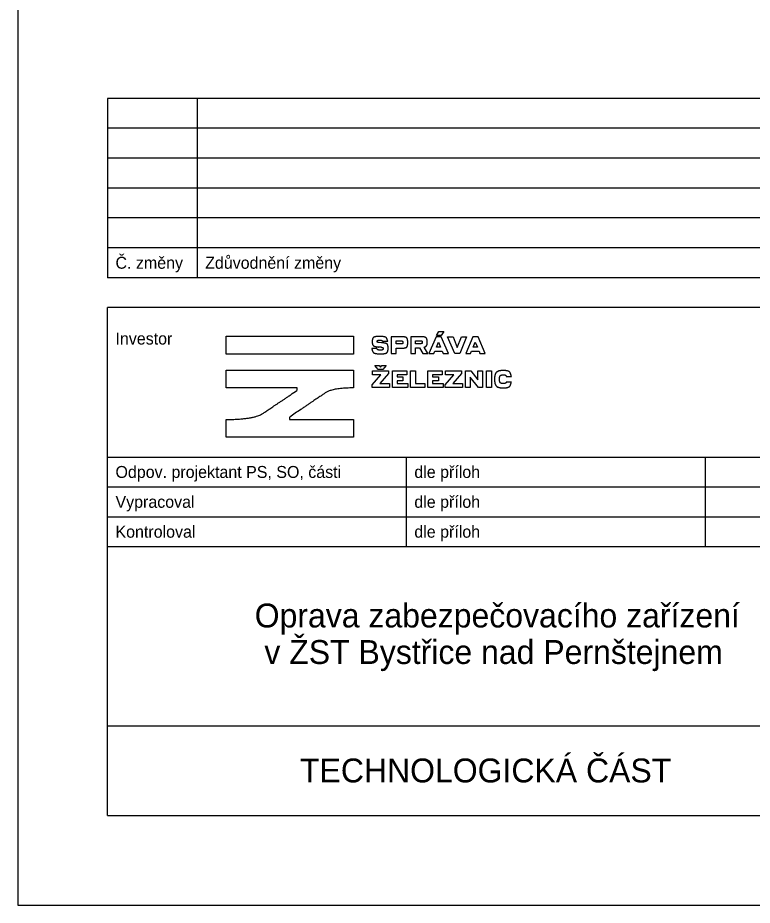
# Model space of a CAD drawing. Extents: x -790471 to -790261, y -986448 to -986151.
# Drawn here: x -790470.6 to -790347.7, y -986447.6 to -986299.1 of the extents above; entities that cross this region are included whole.
import ezdxf

# ---------------------------------------------------------------- set-up
doc = ezdxf.new("R2010")
doc.units = 0
for name, color, linetype in [('logo_sprava_zeleznic', 7, 'Continuous'), ('Ramečky', 7, 'Continuous'), ('Rámečky-tisk', 7, 'Continuous'), ('Text', 7, 'Continuous'), ('Text barevný', 7, 'Continuous')]:
    doc.layers.add(name, color=color, linetype=linetype)

msp = doc.modelspace()

# ---------------------------------------------------------------- linework, layer by layer
at = {"layer": 'logo_sprava_zeleznic'}
for p, q in [((-790400.56, -986352.26), (-790400.12, -986351.6)), ((-790400.12, -986351.6), (-790399.3, -986351.6)), ((-790399.3, -986351.6), (-790399.78, -986352.26)), ((-790409.51, -986353.23), (-790408.69, -986353.23)), ((-790399.78, -986352.26), (-790400.56, -986352.26)), ((-790398.7, -986352.48), (-790397.76, -986352.48)), ((-790397.49, -986355.29), (-790398.7, -986352.48)), ((-790397.76, -986352.48), (-790397.05, -986354.28)), ((-790397.05, -986354.28), (-790396.34, -986352.48)), ((-790395.49, -986352.48), (-790396.64, -986355.29)), ((-790396.34, -986352.48), (-790395.49, -986352.48)), ((-790410.51, -986354.45), (-790411.36, -986354.45)), ((-790409.76, -986353.48), (-790410.15, -986353.45)), ((-790396.64, -986355.29), (-790397.49, -986355.29)), ((-790410.29, -986357.96), (-790410.83, -986357.28)), ((-790410.83, -986357.28), (-790410.14, -986357.28)), ((-790410.14, -986357.28), (-790409.91, -986357.56)), ((-790409.91, -986357.56), (-790409.68, -986357.28)), ((-790409.68, -986357.28), (-790408.97, -986357.28)), ((-790408.97, -986357.28), (-790409.53, -986357.96)), ((-790411.3, -986360.53), (-790409.84, -986358.86)), ((-790411.26, -986358.17), (-790408.55, -986358.17)), ((-790411.26, -986358.86), (-790411.26, -986358.17)), ((-790409.84, -986358.86), (-790411.26, -986358.86)), ((-790409.53, -986357.96), (-790410.29, -986357.96)), ((-790408.55, -986358.63), (-790410.02, -986360.29)), ((-790408.55, -986358.17), (-790408.55, -986358.63)), ((-790407.92, -986358.17), (-790405.49, -986358.17)), ((-790407.92, -986360.99), (-790407.92, -986358.17)), ((-790405.49, -986358.83), (-790407.1, -986358.83)), ((-790407.1, -986358.83), (-790407.1, -986359.2)), ((-790407.1, -986359.2), (-790406.14, -986359.2)), ((-790406.14, -986359.2), (-790406.14, -986359.87)), ((-790405.49, -986358.17), (-790405.49, -986358.83)), ((-790404.86, -986358.17), (-790404.05, -986358.17)), ((-790404.86, -986360.99), (-790404.86, -986358.17)), ((-790404.05, -986358.17), (-790404.05, -986360.28)), ((-790401.99, -986358.17), (-790399.57, -986358.17)), ((-790401.99, -986360.99), (-790401.99, -986358.17)), ((-790399.57, -986358.83), (-790401.18, -986358.83)), ((-790401.18, -986358.83), (-790401.18, -986359.2)), ((-790401.18, -986359.2), (-790400.22, -986359.2)), ((-790400.22, -986359.2), (-790400.22, -986359.87)), ((-790399.57, -986358.17), (-790399.57, -986358.83)), ((-790399.07, -986360.53), (-790397.61, -986358.86)), ((-790399.03, -986358.17), (-790396.33, -986358.17)), ((-790399.03, -986358.86), (-790399.03, -986358.17)), ((-790397.61, -986358.86), (-790399.03, -986358.86)), ((-790396.33, -986358.63), (-790397.8, -986360.29)), ((-790396.33, -986358.17), (-790396.33, -986358.63)), ((-790395.69, -986358.17), (-790394.78, -986358.17)), ((-790395.69, -986360.99), (-790395.69, -986358.17)), ((-790393.53, -986360.99), (-790394.89, -986359.26)), ((-790394.89, -986359.26), (-790394.89, -986360.99)), ((-790394.78, -986358.17), (-790393.63, -986359.68)), ((-790393.63, -986359.68), (-790393.63, -986358.17)), ((-790393.63, -986358.17), (-790392.85, -986358.17)), ((-790392.85, -986358.17), (-790392.85, -986360.99)), ((-790388.84, -986359.12), (-790388.01, -986359.12)), ((-790411.3, -986360.99), (-790411.3, -986360.53)), ((-790410.02, -986360.29), (-790408.39, -986360.29)), ((-790408.39, -986360.29), (-790408.39, -986360.99)), ((-790406.14, -986359.87), (-790407.1, -986359.87)), ((-790407.1, -986359.87), (-790407.1, -986360.3)), ((-790407.1, -986360.3), (-790405.34, -986360.3)), ((-790405.34, -986360.3), (-790405.34, -986360.99)), ((-790404.05, -986360.28), (-790402.47, -986360.28)), ((-790402.47, -986360.28), (-790402.47, -986360.99)), ((-790400.22, -986359.87), (-790401.18, -986359.87)), ((-790401.18, -986359.87), (-790401.18, -986360.3)), ((-790401.18, -986360.3), (-790399.41, -986360.3)), ((-790399.41, -986360.3), (-790399.41, -986360.99)), ((-790399.07, -986360.99), (-790399.07, -986360.53)), ((-790397.8, -986360.29), (-790396.16, -986360.29)), ((-790396.16, -986360.29), (-790396.16, -986360.99)), ((-790388.01, -986360.05), (-790388.83, -986360.05)), ((-790408.39, -986360.99), (-790411.3, -986360.99)), ((-790405.34, -986360.99), (-790407.92, -986360.99)), ((-790402.47, -986360.99), (-790404.86, -986360.99)), ((-790399.41, -986360.99), (-790401.99, -986360.99)), ((-790396.16, -986360.99), (-790399.07, -986360.99)), ((-790394.89, -986360.99), (-790395.69, -986360.99)), ((-790392.85, -986360.99), (-790393.53, -986360.99))]:
    msp.add_line(p, q, dxfattribs=at)
for points in [[(-790435.73, -986352.4), (-790414.41, -986352.4), (-790414.41, -986355.38), (-790435.73, -986355.38)], [(-790401.8, -986355.29), (-790400.98, -986355.29), (-790400.82, -986354.89), (-790399.57, -986354.89), (-790399.41, -986355.29), (-790398.53, -986355.29), (-790399.73, -986352.48), (-790400.6, -986352.48)], [(-790395.65, -986355.29), (-790394.83, -986355.29), (-790394.66, -986354.89), (-790393.42, -986354.89), (-790393.26, -986355.29), (-790392.38, -986355.29), (-790393.57, -986352.48), (-790394.45, -986352.48)], [(-790400.19, -986353.39), (-790399.85, -986354.23), (-790400.54, -986354.23)], [(-790394.04, -986353.39), (-790393.7, -986354.23), (-790394.39, -986354.23)], [(-790392.16, -986358.17), (-790391.35, -986358.17), (-790391.35, -986360.99), (-790392.16, -986360.99)]]:
    msp.add_lwpolyline(points, close=True, dxfattribs=at)
for points in [[(-790406.38, -986352.48), (-790408.11, -986352.48), (-790408.11, -986355.29), (-790407.3, -986355.29), (-790407.3, -986354.39), (-790406.38, -986354.39)], [(-790406.48, -986353.69), (-790407.3, -986353.69), (-790407.3, -986353.17), (-790406.48, -986353.17)], [(-790403.12, -986352.48), (-790404.84, -986352.48), (-790404.84, -986355.29), (-790404.03, -986355.29), (-790404.03, -986354.31), (-790403.39, -986354.31), (-790402.84, -986355.29), (-790401.98, -986355.29), (-790402.59, -986354.22)], [(-790403.22, -986353.64), (-790404.03, -986353.64), (-790404.03, -986353.16), (-790403.22, -986353.16)], [(-790423.87, -986361.46), (-790423.87, -986361.04), (-790435.73, -986361.04), (-790435.73, -986358.07), (-790414.41, -986358.07), (-790414.41, -986361.04)], [(-790425.1, -986365.91), (-790425.1, -986366.32), (-790414.41, -986366.32), (-790414.41, -986369.3), (-790435.73, -986369.3), (-790435.73, -986366.32), (-790435.71, -986366.32)]]:
    msp.add_lwpolyline(points, dxfattribs=at)
for centre, radius, start, end in [((-790411.9, -986375.14), 21.01, 84.2634, 85.3384), ((-790461.18, -986308.6), 64.69, 304.0901, 305.2133), ((-790124.63, -986802.54), 530.02, 124.292, 124.5333)]:
    msp.add_arc(centre, radius, start, end, dxfattribs=at)
for points in [[(-790410.05, -986352.42), (-790410.77, -986352.42), (-790411.29, -986352.71), (-790411.29, -986353.28)], [(-790411.29, -986353.28), (-790411.29, -986353.83), (-790410.87, -986354.14), (-790410.19, -986354.2)], [(-790410.46, -986353.24), (-790410.46, -986353.12), (-790410.3, -986353.06), (-790410.05, -986353.06)], [(-790410.15, -986353.45), (-790410.35, -986353.43), (-790410.46, -986353.36), (-790410.46, -986353.24)], [(-790408.69, -986353.23), (-790408.77, -986352.87), (-790409.09, -986352.42), (-790410.05, -986352.42)], [(-790410.05, -986353.06), (-790409.73, -986353.06), (-790409.55, -986353.17), (-790409.51, -986353.23)], [(-790406.48, -986353.17), (-790406.27, -986353.17), (-790406.17, -986353.26), (-790406.17, -986353.43)], [(-790405.34, -986353.43), (-790405.34, -986352.8), (-790405.73, -986352.48), (-790406.38, -986352.48)], [(-790403.22, -986353.16), (-790403.02, -986353.16), (-790402.91, -986353.23), (-790402.91, -986353.4)], [(-790402.08, -986353.4), (-790402.08, -986352.79), (-790402.49, -986352.48), (-790403.12, -986352.48)], [(-790411.36, -986354.45), (-790411.29, -986354.84), (-790410.93, -986355.34), (-790409.92, -986355.34)], [(-790409.92, -986354.71), (-790410.28, -986354.71), (-790410.46, -986354.57), (-790410.51, -986354.45)], [(-790409.92, -986355.34), (-790409.08, -986355.34), (-790408.63, -986355), (-790408.63, -986354.4)], [(-790409.47, -986354.46), (-790409.47, -986354.61), (-790409.6, -986354.71), (-790409.92, -986354.71)], [(-790409.8, -986354.23), (-790409.6, -986354.26), (-790409.47, -986354.31), (-790409.47, -986354.46)], [(-790408.63, -986354.4), (-790408.63, -986353.79), (-790409.03, -986353.53), (-790409.76, -986353.48)], [(-790406.17, -986353.43), (-790406.17, -986353.59), (-790406.27, -986353.69), (-790406.48, -986353.69)], [(-790406.38, -986354.39), (-790405.73, -986354.39), (-790405.34, -986354.06), (-790405.34, -986353.43)], [(-790402.91, -986353.4), (-790402.91, -986353.55), (-790403.02, -986353.64), (-790403.22, -986353.64)], [(-790402.59, -986354.22), (-790402.27, -986354.08), (-790402.08, -986353.8), (-790402.08, -986353.4)], [(-790389.36, -986358.13), (-790390.22, -986358.13), (-790390.82, -986358.73), (-790390.82, -986359.58)], [(-790390, -986359.58), (-790390, -986359.18), (-790389.76, -986358.85), (-790389.36, -986358.85)], [(-790388.01, -986359.12), (-790388.06, -986358.8), (-790388.4, -986358.13), (-790389.36, -986358.13)], [(-790389.36, -986358.85), (-790389.02, -986358.85), (-790388.88, -986359.05), (-790388.84, -986359.12)], [(-790390.82, -986359.58), (-790390.82, -986360.43), (-790390.22, -986361.04), (-790389.36, -986361.04)], [(-790389.36, -986360.31), (-790389.76, -986360.31), (-790390, -986359.99), (-790390, -986359.58)], [(-790389.36, -986361.04), (-790388.37, -986361.04), (-790388.05, -986360.31), (-790388.01, -986360.05)], [(-790388.83, -986360.05), (-790388.87, -986360.12), (-790389.02, -986360.31), (-790389.36, -986360.31)], [(-790435.71, -986366.32), (-790431.06, -986366.31), (-790428.08, -986364.3), (-790424.92, -986362.18)], [(-790414.41, -986361.04), (-790417.9, -986361.04), (-790420.38, -986362.71), (-790423.25, -986364.65)]]:
    msp.add_open_spline(points, degree=2, dxfattribs=at)
at = {"layer": 'Ramečky'}
for p, q in [((-790275.59, -986312.6), (-790455.59, -986312.6)), ((-790455.59, -986312.6), (-790455.59, -986342.6)), ((-790440.59, -986312.6), (-790440.59, -986342.6)), ((-790305.59, -986317.6), (-790455.59, -986317.6)), ((-790305.59, -986322.6), (-790455.59, -986322.6)), ((-790305.59, -986327.6), (-790455.59, -986327.6)), ((-790305.59, -986332.6), (-790455.59, -986332.6)), ((-790305.59, -986337.6), (-790455.59, -986337.6)), ((-790275.59, -986342.6), (-790455.59, -986342.6)), ((-790275.59, -986347.6), (-790455.59, -986347.6)), ((-790455.59, -986432.6), (-790455.59, -986347.6)), ((-790455.59, -986372.6), (-790325.59, -986372.6)), ((-790455.59, -986377.6), (-790325.59, -986377.6)), ((-790455.59, -986382.6), (-790325.59, -986382.6)), ((-790455.59, -986387.6), (-790325.59, -986387.6)), ((-790455.59, -986417.6), (-790275.59, -986417.6)), ((-790455.59, -986432.6), (-790275.59, -986432.6))]:
    msp.add_line(p, q, dxfattribs=at)
for points in [[(-790405.59, -986372.6), (-790405.59, -986387.6)], [(-790355.59, -986372.6), (-790355.59, -986387.6)]]:
    msp.add_lwpolyline(points, dxfattribs=at)
at = {"layer": 'Rámečky-tisk'}
msp.add_line((-790470.59, -986150.6), (-790470.59, -986447.6), dxfattribs=at)
msp.add_lwpolyline([(-790470.59, -986447.6), (-790260.59, -986447.6), (-790260.59, -986150.6)], dxfattribs=at)

# ---------------------------------------------------------------- texts
at = {"layer": 'Text'}
for s, p in [('Č. změny', (-790454.24, -986341.1)), ('Zdůvodnění změny', (-790439.24, -986341.1)), ('Investor', (-790454.24, -986353.78)), ('Odpov. projektant PS, SO, části', (-790454.24, -986376.1)), ('dle příloh', (-790404.24, -986376.1)), ('Vypracoval', (-790454.24, -986381.1)), ('dle příloh', (-790404.24, -986381.1)), ('Kontroloval', (-790454.24, -986386.1)), ('dle příloh', (-790404.24, -986386.1))]:
    msp.add_text(s, height=2, dxfattribs=at).set_placement(p)
at = {"layer": 'Text barevný'}
for s, p in [('Oprava zabezpečovacího zařízení', (-790430.95, -986401.12)), ('v ŽST Bystřice nad Pernštejnem', (-790429.33, -986407.23)), ('TECHNOLOGICKÁ ČÁST', (-790423.37, -986427.05))]:
    msp.add_text(s, height=4, dxfattribs=at).set_placement(p)

doc.saveas('drawing.dxf')
